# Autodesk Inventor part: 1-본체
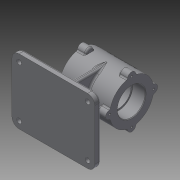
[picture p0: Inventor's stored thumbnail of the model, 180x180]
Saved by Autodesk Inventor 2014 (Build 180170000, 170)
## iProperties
Created: 2015-12
Part Number: 1-본체
Material: Generic
Document SubType Name: Modeling
Designer: test_24
Density: 1 g/cm^3
Appearance: Default
Author: test_24
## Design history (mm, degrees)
sketch "스케치1"
  geometry: L1 (-42.5, 0)-(42.5, 0); L2 (-42.5, 23.5)-(-20.5, 23.5); L3 (-20.5, 23.5)-(-20.5, 21); L4 (-20.5, 21)-(20.5, 21); L5 (20.5, 21)-(20.5, 23.5); L6 (20.5, 23.5)-(42.5, 23.5); L7 (42.5, 23.5)-(42.5, 37); L8 (42.5, 37)-(-42.5, 37); L9 (-42.5, 37)-(-42.5, 23.5); L10 (-42.5, 37)-(-42.5, 44.041); 2 further points
  constraints: 20 end point, 6 parallel, 3 collinear, 2 midpoint, 1 horizontal, 1 perpendicular, 1 point on line
  dimensions: "d0" = 85 distance between parallel lines of L7 L9; "d1" = 22 distance of L2.start L2.end; "d2" = 22 distance of L5.end L6.end; "d3" = 42 diameter of L4 L1; "d4" = 47 diameter of L6 L1; "d5" = 74 diameter of L8 L1; "d47" = 85 distance of L1.start L1.end; "d48" = 42.5 distance of point (0, 0) L1.start
revolve "회전1" sketch "스케치1" stored, may be unused: angle "d8" = 90 deg
node "작업 평면1"
sketch "스케치2"
  geometry: L1 (60, 55)-(-80, 55); L2 (-80, 55)-(-80, -55); L3 (-80, -55)-(60, -55); L4 (60, -55)-(60, 55); L5 (-42.5, 37)-(42.5, 37) reference; L6 (-42.5, -37)-(-42.5, 37) reference; 1 further point
  constraints: 8 end point, 2 parallel, 1 horizontal, 1 perpendicular
  dimensions: "d10" = 110 distance of L3.end L1.start; "d11" = 140 distance of L1.start L1.end; "d17" = 55 distance from line of point (0, 0) L1; "d18" = 37.5 distance between parallel lines of L6 L2
extrude "돌출1" join sketch "스케치2" distance "d14" = 10; taper "d15" = 0 deg
sketch "스케치6"
  geometry: L1 (-70, -55)-(-70, 55) reference; L2 (0, 37)-(-70, 37); L3 (0, -37)-(-70, -37); A1 r 37 centre (0, 0) between (0, 37) and (0, -37) reference; 1 further point
  constraints: 4 end point, 2 perpendicular, 2 point on circle, 2 point on line, 2 tangent
extrude "돌출3" join sketch "스케치6" stored distance "d22" = 8; taper "d23" = 0 deg
sketch "스케치7"
  geometry: L1 (-42.5, -37)-(42.5, -37) reference; L2 (60, -70)-(-80, -70) reference; L3 (-25, -70)-(-20.948, -37); L4 (20.948, -37)-(25, -70); 1 further point
  constraints: 4 end point, 4 point on line
  dimensions: "d24" = 97 deg angle of L2 L4; "d25" = 97 deg angle of L2 L3; "d62" = 25 horizontal distance of point (0, 0) L3.start; "d63" = 25 horizontal distance of L4.end point (0, 0)
feature "리브1" dims "d29" = 1, "d30" = 12, "d31" = 0, "d32" = 0, "d33" = 1, "d34" = 1
feature "리브2" dims "d35" = 1, "d36" = 12, "d37" = 0, "d38" = 0, "d39" = 1, "d40" = 1
sketch "스케치9"
  geometry: L1 (0, 37)-(0, -37); L2 (-37, 0)-(37, 0); A1 r 7 centre (0, 37) between (6.969, 36.338) and (-6.969, 36.338); A2 r 7 centre (37, 0) between (36.338, -6.969) and (36.338, 6.969); A3 r 7 centre (-37, 0) between (-36.338, 6.969) and (-36.338, -6.969); A4 r 7 centre (0, -37) between (-6.969, -36.338) and (6.969, -36.338); 3 further points
  constraints: 8 point on circle, 4 centre point, 4 end point, 4 midpoint, 3 coincident, 1 equal radius, 1 horizontal alignment, 1 perpendicular, 1 vertical, 13 other
  dimensions: "d42" = 14 diameter of A1; "d43" = 14 diameter of A3; "d44" = 14 diameter of A4
extrude "돌출4" join sketch "스케치9" distance "d45" = 15; taper "d46" = 0 deg
fillet "모깎기1" dims "d49" = 12
sketch "스케치10"
  geometry: L1 (48, 55)-(-68, 55) reference; L2 (-80, 43)-(-80, -43) reference; C1 r 4 at (-68, 43); 1 further point
  constraints: 1 centre point
  dimensions: "d51" = 12 distance from line of L1 C1.centre; "d52" = 12 distance from line of C1.centre L2; "d53" = 8 diameter of C1
extrude "돌출5" cut sketch "스케치10" distance "d54" = 15; taper "d55" = 0 deg
sketch "스케치11"
  geometry: A1 r 7 centre (0, 0) between (0.662, 6.969) and (0.662, -6.969) reference; A2 r 7 centre (37, -37) between (30.031, -36.338) and (43.969, -36.338) reference; A3 r 7 centre (74, 0) between (73.338, -6.969) and (73.338, 6.969) reference; A4 r 7 centre (37, 37) between (43.969, 36.338) and (30.031, 36.338) reference; 4 further points
  constraints: 4 coincident
hole "구멍1" sketch "스케치11" at (37, 37), (74, 0), (37, -37), (0, 0) diameter "d64" = 3.242; stored, may be unused: countersink angle "d68" = 90 deg, drill point angle "d70" = 118 deg; dims "d65" = 9, "d66" = 4, "d67" = 2, "d69" = 11
chamfer "모따기1" distance "d71" = 1; stored, may be unused: second distance "d72" = 2, angle "d73" = 45 deg
fillet "모깎기2" dims "d74" = 0.3
fillet "모깎기3" dims "d75" = 3
fillet "모깎기4" dims "d76" = 3
fillet "모깎기5" dims "d77" = 3
fillet "모깎기6" dims "d78" = 3
fillet "모깎기7" dims "d79" = 3
fillet "모깎기8" dims "d80" = 3
node "작업 평면5"
sketch "스케치12"
  geometry: L1 (0, -67)-(0, 0) reference; L2 (0, 0)-(37, 0); L3 (37, 0)-(10.837, 26.163); A1 r 37 centre (37, 0) between (27.896, 35.863) and (1.138, 9.104) reference; A2 r 37 centre (37, 0) between (72.862, 9.104) and (46.104, 35.862) reference; A3 r 37 centre (37, 0) between (41.188, 36.762) and (32.812, 36.762) reference; 1 further point
  constraints: 4 end point, 1 perpendicular, 1 point on circle
  dimensions: "d82" = 45 deg angle of L2 L3
node "작업 평면6"
sketch "스케치13"
  geometry: 2 further points
  constraints: 1 other
feature "엠보싱1" sketch "스케치13" dims "d83" = 0.5, "d84" = 0
fillet "모깎기9" dims "d85" = 3
fillet "모깎기10" dims "d86" = 3
node "솔리드1"
pattern_linear "직사각형 패턴1" dims "d58" = 116
pattern_linear "직사각형 패턴2" dims "d61" = 86
mirror "대칭1"
mirror "대칭2"
